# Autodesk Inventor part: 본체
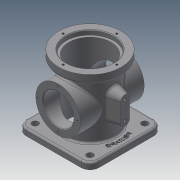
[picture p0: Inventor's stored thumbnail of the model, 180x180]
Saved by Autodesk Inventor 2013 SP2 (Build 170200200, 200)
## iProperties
Created: 2021-03
Part Number: 본체
Material: Generic
Document SubType Name: Modeling
Designer: kumcom13
Density: 1 g/cm^3
Mass: 311.967 g
Surface Area: 879.783 cm^2
Volume: 311.967 cm^3
Author: kumcom13
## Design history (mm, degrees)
sketch "스케치1"
  geometry: L1 (-57, 57)-(57, 57); L2 (57, 57)-(57, -57); L3 (57, -57)-(-57, -57); L4 (-57, -57)-(-57, 57); L5 (-57, 57)-(57, -57); L6 (57, 57)-(-57, -57); 1 further point
  constraints: 12 end point, 2 midpoint, 2 parallel, 1 horizontal, 1 perpendicular
  dimensions: "d0" = 114 distance of L2.end L3.end; "d1" = 114 distance of L1.end L2.end
extrude "돌출1" new body sketch "스케치1" distance "d2" = 10; taper "d3" = 0 deg
sketch "스케치2"
  geometry: C1 r 38 at (0, 0); 1 further point
  constraints: 1 centre point, 1 coincident
  dimensions: "d4" = 76 diameter of C1
extrude "돌출2" join sketch "스케치2" distance "d5" = 101; taper "d6" = 0 deg
sketch "스케치3"
  geometry: C1 r 38 at (0, 0) reference; C2 r 49 at (0, 0)
  constraints: 1 centre point, 1 coincident
  dimensions: "d7" = 98 diameter of C2
extrude "돌출3" join sketch "스케치3" distance "d8" = 13; taper "d9" = 0 deg
sketch "스케치4"
  geometry: C1 r 49 at (0, 0) reference; C2 r 37 at (0, 0)
  constraints: 1 centre point, 1 coincident
  dimensions: "d10" = 74 diameter of C2
extrude "돌출4" cut sketch "스케치4" distance "d11" = 7; taper "d12" = 0 deg
sketch "스케치5"
  geometry: C1 r 37 at (0, 0) reference; C2 r 33 at (0, 0)
  constraints: 1 centre point, 1 coincident
  dimensions: "d13" = 66 diameter of C2
extrude "돌출5" cut sketch "스케치5" stored distance "d14" = 7; taper "d15" = 0 deg
sketch "스케치6"
  geometry: L1 (0, 0)-(0, 42); C1 r 49 at (0, 0) reference; 1 further point
  constraints: 2 end point, 1 coincident, 1 vertical
  dimensions: "d16" = 42 distance of L1.start L1.end
hole "구멍1" sketch "스케치6" at (0, 42) diameter "d17" = 3.242; stored, may be unused: countersink angle "d21" = 90 deg, drill point angle "d23" = 118 deg; dims "d18" = 6, "d19" = 4, "d20" = 2, "d22" = 8
node "작업 평면1"
sketch "스케치7"
  geometry: L1 (0, 0)-(54, 0); C1 r 35 at (54, 0)
  constraints: 2 end point, 1 centre point, 1 coincident, 1 horizontal
  dimensions: "d28" = 54 distance of L1.start L1.end; "d29" = 70 diameter of C1
extrude "돌출6" join sketch "스케치7" stored distance "d30" = 7; taper "d31" = 0 deg
sketch "스케치8"
  geometry: L1 (0, 0)-(0, 31); C1 r 35 at (0, 0) reference; 2 further points
  constraints: 2 end point, 1 coincident, 1 vertical
  dimensions: "d32" = 31 distance of L1.start L1.end
hole "구멍2" sketch "스케치8" at (0, 31) diameter "d33" = 3.242; stored, may be unused: countersink angle "d37" = 90 deg, drill point angle "d39" = 118 deg; dims "d34" = 6, "d35" = 4, "d36" = 2, "d38" = 8
sketch "스케치9"
  geometry: C1 r 35 at (0, 0) reference; C2 r 24 at (0, 0); 1 further point
  constraints: 1 centre point, 1 coincident
  dimensions: "d43" = 48 diameter of C2
extrude "돌출7" cut sketch "스케치9" stored distance "d44" = 7; taper "d45" = 0 deg
fillet "모깎기1" dims "d46" = 14
sketch "스케치10"
  geometry: C1 r 5 at (43, 43); C2 r 5 at (-43, 43); C3 r 5 at (-43, -43); C4 r 5 at (43, -43); A1 r 14 centre (43, 43) between (57, 43) and (43, 57) reference; A2 r 14 centre (-43, 43) between (-43, 57) and (-57, 43) reference; A3 r 14 centre (-43, -43) between (-57, -43) and (-43, -57) reference; A4 r 14 centre (43, -43) between (43, -57) and (57, -43) reference
  constraints: 4 centre point, 4 coincident
  dimensions: "d47" = 10 diameter of C1; "d48" = 10 diameter of C2; "d49" = 10 diameter of C3; "d50" = 10 diameter of C4
extrude "돌출8" cut sketch "스케치10" stored distance "d51" = 7; taper "d52" = 0 deg
node "작업 평면2"
sketch "스케치11"
  geometry: L1 (0, 0)-(0, 54); L2 (0, 77)-(0, 77); L3 (7, 70)-(7, 41); L4 (0, 34)-(0, 34); L5 (-7, 41)-(-7, 70); L6 (7, 34)-(7, 54); L7 (7, 54)-(0, 54); A1 r 7 centre (0, 70) between (7, 70) and (0, 77); A2 r 7 centre (0, 70) between (0, 77) and (-7, 70); A3 r 7 centre (0, 41) between (-7, 41) and (0, 34); A4 r 7 centre (0, 41) between (0, 34) and (7, 41); 3 further points
  constraints: 14 end point, 9 point on line, 8 point on circle, 8 tangent, 4 centre point, 3 equal radius, 2 parallel, 2 perpendicular, 1 horizontal, 1 vertical
  dimensions: "d54" = 54 distance of L1.start L1.end; "d55" = 14 distance of L6.start point (-7, 34); "d56" = 43 distance of point (7, 77) L6.start; "d57" = 20 distance of L6.start L6.end; "d58" = 7 distance of L1.end L6.end; "d61" = 7 radius of A1
extrude "돌출9" join sketch "스케치11" stored distance "d59" = 7; taper "d60" = 15 deg
sketch "스케치12"
  geometry: A1 r 7 centre (0, 70) between (7, 70) and (-7, 70) reference; A2 r 7 centre (0, 41) between (-7, 41) and (7, 41) reference; 3 further points
  constraints: 2 coincident
hole "구멍3" sketch "스케치12" at (0, 70), (0, 41) diameter "d62" = 4.134; stored, may be unused: countersink angle "d66" = 90 deg, drill point angle "d68" = 118 deg; dims "d63" = 8, "d64" = 4, "d65" = 2, "d67" = 10
sketch "스케치13"
  geometry: C1 r 38 at (0, 0) reference; C2 r 50 at (0, 0)
  constraints: 1 centre point, 1 coincident, 1 other
  dimensions: "d69" = 100 diameter of C2
feature "엠보싱1" sketch "스케치13" dims "d0" = 114, "d1" = 114, "d10" = 74, "d70" = 0.5, "d71" = 0
chamfer "모따기1" distance "d72" = 1; stored, may be unused: second distance "d73" = 2, angle "d74" = 45 deg
fillet "모깎기2" dims "d75" = 3
fillet "모깎기3" dims "d76" = 3
node "솔리드1"
pattern_circular "원형 패턴1" dims angle "d25" = 360 deg
pattern_circular "원형 패턴2" dims angle "d41" = 360 deg
mirror "대칭1"
other parameters: "d53" = 55
